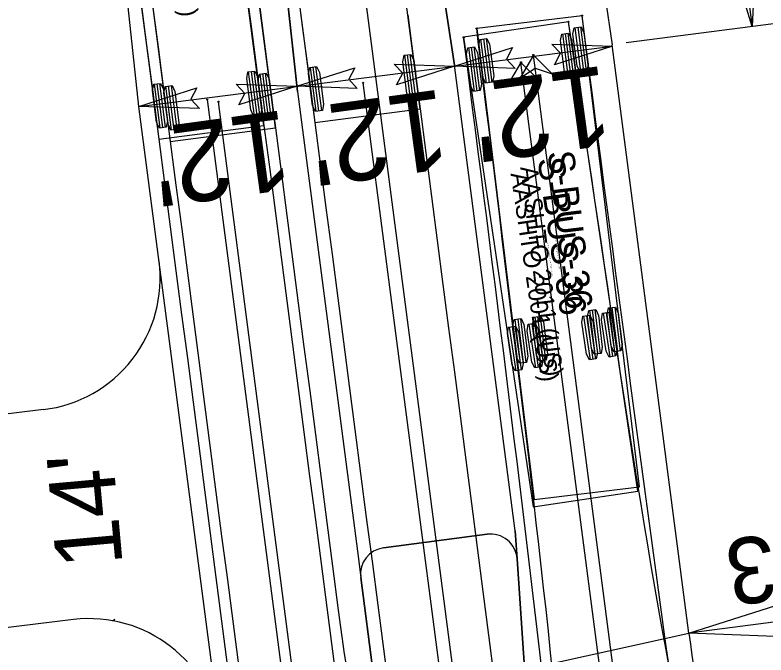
# Model space of a CAD drawing. Extents: x 2367848 to 2369479, y 800728 to 808616.
# Drawn here: x 2368338.9 to 2368395.5, y 808026 to 808074.3 of the extents above; entities that cross this region are included whole.
import ezdxf

# ---------------------------------------------------------------- set-up
doc = ezdxf.new("R2010")
doc.units = 0
for name, color, linetype in [('Prop AutoTurn Projected Path', 7, 'Continuous'), ('Prop AutoTurn Simulation', 7, 'Continuous'), ('Prop Conc 5in Monolithic Surface Mount Island', 7, 'Continuous'), ('Prop Dimension', 7, 'Continuous'), ('Prop Dimension Text', 7, 'Continuous'), ('Prop EOT', 7, 'Continuous'), ('Prop Horizontal Alignment', 7, 'Continuous'), ('Prop Lane Lines', 7, 'Continuous'), ('Prop Paint Stripe', 7, 'Continuous'), ('Prop Terminator CELL', 7, 'Continuous'), ('Scratch_Level_1', 7, 'Continuous'), ('Scratch_Level_3', 7, 'Continuous')]:
    doc.layers.add(name, color=color, linetype=linetype)

msp = doc.modelspace()

# ---------------------------------------------------------------- linework, layer by layer
at = {"layer": 'Prop AutoTurn Projected Path'}
for p, q in [((2368386.918, 807995.035), (2368377.058, 808070.767)), ((2368376.879, 807979.194), (2368365.158, 808069.218)), ((2368363.77, 807994.679), (2368354.25, 808067.798))]:
    msp.add_line(p, q, dxfattribs=at)
at = {"layer": 'Prop AutoTurn Simulation'}
for p, q in [((2368369.447, 808067.255), (2368364.825, 808102.755)), ((2368356.892, 808101.723), (2368361.514, 808066.222)), ((2368358.539, 808065.835), (2368353.917, 808101.335)), ((2368345.984, 808100.302), (2368350.606, 808064.802)), ((2368380.649, 808073.825), (2368372.735, 808072.655)), ((2368385.884, 808038.41), (2368380.649, 808073.825)), ((2368372.735, 808072.655), (2368377.97, 808037.24)), ((2368372.735, 808072.655), (2368372.735, 808072.655)), ((2368380.182, 808072.91), (2368380.612, 808069.604)), ((2368380.388, 808072.937), (2368380.819, 808069.631)), ((2368380.595, 808072.963), (2368381.025, 808069.658)), ((2368373.09, 808071.876), (2368373.521, 808068.571)), ((2368373.297, 808071.903), (2368373.727, 808068.597)), ((2368373.503, 808071.93), (2368373.934, 808068.624)), ((2368368.72, 808068.001), (2368368.29, 808071.306)), ((2368368.927, 808068.028), (2368368.496, 808071.333)), ((2368369.133, 808068.055), (2368368.703, 808071.36)), ((2368361.613, 808067.075), (2368361.183, 808070.381)), ((2368361.82, 808067.102), (2368361.39, 808070.408)), ((2368362.027, 808067.129), (2368361.596, 808070.435)), ((2368357.812, 808066.581), (2368357.382, 808069.886)), ((2368358.019, 808066.607), (2368357.588, 808069.913)), ((2368358.225, 808066.634), (2368357.795, 808069.94)), ((2368350.705, 808065.655), (2368350.275, 808068.961)), ((2368350.912, 808065.682), (2368350.482, 808068.988)), ((2368351.119, 808065.709), (2368350.688, 808069.015)), ((2368361.514, 808066.222), (2368369.447, 808067.255)), ((2368369.447, 808067.255), (2368369.447, 808067.255)), ((2368350.606, 808064.802), (2368358.539, 808065.835)), ((2368358.539, 808065.835), (2368358.539, 808065.835)), ((2368381.99, 808051.649), (2368382.477, 808048.352)), ((2368382.196, 808051.68), (2368382.683, 808048.382)), ((2368383.267, 808051.838), (2368383.755, 808048.541)), ((2368383.474, 808051.869), (2368383.961, 808048.571)), ((2368383.68, 808051.899), (2368384.167, 808048.602)), ((2368381.784, 808051.619), (2368382.271, 808048.321)), ((2368376.178, 808050.79), (2368376.665, 808047.493)), ((2368376.384, 808050.821), (2368376.871, 808047.523)), ((2368376.59, 808050.851), (2368377.077, 808047.554)), ((2368377.662, 808051.01), (2368378.149, 808047.712)), ((2368377.868, 808051.04), (2368378.355, 808047.743)), ((2368378.074, 808051.071), (2368378.561, 808047.773)), ((2368377.97, 808037.24), (2368385.884, 808038.41))]:
    msp.add_line(p, q, dxfattribs=at)
for points in [[(2368360.128, 808076.872), (2368360.59, 808073.322), (2368361.052, 808069.772), (2368361.514, 808066.222), (2368361.514, 808066.222), (2368361.514, 808066.222), (2368361.945, 808062.913), (2368362.376, 808059.603), (2368362.807, 808056.293), (2368363.238, 808052.983), (2368363.669, 808049.674), (2368364.1, 808046.364), (2368364.531, 808043.054), (2368364.962, 808039.745), (2368365.393, 808036.435), (2368365.824, 808033.125), (2368366.254, 808029.816), (2368366.685, 808026.506), (2368367.116, 808023.196)], [(2368357.153, 808076.485), (2368357.615, 808072.935), (2368358.077, 808069.385), (2368358.539, 808065.835), (2368358.539, 808065.835), (2368358.97, 808062.526), (2368359.401, 808059.218), (2368359.832, 808055.909), (2368360.263, 808052.601), (2368360.693, 808049.292), (2368361.124, 808045.984), (2368361.555, 808042.675), (2368361.986, 808039.367), (2368362.416, 808036.058), (2368362.847, 808032.75), (2368363.278, 808029.441), (2368363.732, 808026.136), (2368364.284, 808022.842)], [(2368349.22, 808075.452), (2368349.682, 808071.902), (2368350.144, 808068.352), (2368350.606, 808064.802), (2368350.606, 808064.802), (2368350.606, 808064.802), (2368351.037, 808061.494), (2368351.468, 808058.185), (2368351.899, 808054.876), (2368352.329, 808051.568), (2368352.76, 808048.259), (2368353.191, 808044.951), (2368353.622, 808041.642), (2368354.053, 808038.334), (2368354.483, 808035.025), (2368354.914, 808031.717), (2368355.345, 808028.408), (2368355.776, 808025.1)], [(2368368.523, 808074.355), (2368368.985, 808070.805), (2368369.447, 808067.255), (2368369.447, 808067.255), (2368369.878, 808063.945), (2368370.309, 808060.636), (2368370.74, 808057.326), (2368371.171, 808054.016), (2368371.602, 808050.707), (2368372.033, 808047.397), (2368372.464, 808044.087), (2368372.895, 808040.778), (2368373.326, 808037.468), (2368373.757, 808034.158), (2368374.187, 808030.849), (2368374.618, 808027.539), (2368375.049, 808024.229)], [(2368388.299, 808024.886), (2368388.007, 808026.448), (2368387.72, 808028.019), (2368387.438, 808029.597), (2368387.16, 808031.183), (2368386.886, 808032.774), (2368386.617, 808034.371), (2368386.351, 808035.973), (2368386.088, 808037.58), (2368385.829, 808039.19), (2368385.572, 808040.805), (2368385.319, 808042.422), (2368385.069, 808044.043), (2368384.82, 808045.667), (2368384.575, 808047.293), (2368384.331, 808048.921), (2368384.089, 808050.552), (2368383.848, 808052.184), (2368383.607, 808053.817), (2368383.365, 808055.452), (2368383.123, 808057.088), (2368382.881, 808058.725), (2368382.639, 808060.364), (2368382.397, 808062.003), (2368382.154, 808063.643), (2368381.912, 808065.283), (2368381.669, 808066.925), (2368381.426, 808068.567), (2368381.184, 808070.209), (2368380.941, 808071.853), (2368380.698, 808073.496), (2368380.649, 808073.825)], [(2368378.589, 808025.417), (2368378.389, 808027.123), (2368378.188, 808028.825), (2368377.986, 808030.523), (2368377.784, 808032.217), (2368377.581, 808033.908), (2368377.378, 808035.597), (2368377.174, 808037.283), (2368376.969, 808038.966), (2368376.764, 808040.647), (2368376.558, 808042.326), (2368376.352, 808044.003), (2368376.145, 808045.678), (2368375.937, 808047.351), (2368375.729, 808049.023), (2368375.521, 808050.694), (2368375.312, 808052.363), (2368375.102, 808054.031), (2368374.893, 808055.698), (2368374.682, 808057.364), (2368374.472, 808059.029), (2368374.261, 808060.694), (2368374.05, 808062.357), (2368373.839, 808064.02), (2368373.627, 808065.681), (2368373.415, 808067.343), (2368373.203, 808069.003), (2368372.99, 808070.664), (2368372.778, 808072.323), (2368372.735, 808072.655)]]:
    msp.add_lwpolyline(points, dxfattribs=at)
for points in [[(2368380.131, 808072.903), (2368380.646, 808072.97), (2368380.862, 808072.528), (2368381.172, 808070.148), (2368381.076, 808069.665), (2368380.561, 808069.598), (2368380.345, 808070.04), (2368380.035, 808072.42)], [(2368373.039, 808071.869), (2368373.554, 808071.936), (2368373.77, 808071.494), (2368374.08, 808069.114), (2368373.985, 808068.631), (2368373.469, 808068.564), (2368373.254, 808069.006), (2368372.944, 808071.386)], [(2368369.184, 808068.061), (2368368.669, 808067.994), (2368368.453, 808068.437), (2368368.143, 808070.817), (2368368.238, 808071.299), (2368368.754, 808071.367), (2368368.97, 808070.924), (2368369.28, 808068.544)], [(2368362.078, 808067.136), (2368361.562, 808067.069), (2368361.347, 808067.511), (2368361.037, 808069.891), (2368361.132, 808070.374), (2368361.647, 808070.441), (2368361.863, 808069.999), (2368362.173, 808067.619)], [(2368377.058, 808070.767), (2368376.055, 808069.036), (2368377.187, 808069.775), (2368378.47, 808069.351)], [(2368358.277, 808066.641), (2368357.761, 808066.574), (2368357.545, 808067.016), (2368357.235, 808069.396), (2368357.331, 808069.879), (2368357.846, 808069.946), (2368358.062, 808069.504), (2368358.372, 808067.124)], [(2368351.17, 808065.716), (2368350.654, 808065.649), (2368350.439, 808066.091), (2368350.129, 808068.471), (2368350.224, 808068.954), (2368350.739, 808069.021), (2368350.955, 808068.579), (2368351.265, 808066.199)], [(2368381.732, 808051.611), (2368382.247, 808051.687), (2368382.47, 808051.249), (2368382.821, 808048.874), (2368382.734, 808048.39), (2368382.22, 808048.314), (2368381.997, 808048.753), (2368381.646, 808051.127)], [(2368383.216, 808051.831), (2368383.731, 808051.907), (2368383.954, 808051.468), (2368384.305, 808049.094), (2368384.218, 808048.609), (2368383.704, 808048.533), (2368383.481, 808048.972), (2368383.13, 808051.346)], [(2368377.611, 808051.002), (2368378.125, 808051.078), (2368378.348, 808050.639), (2368378.699, 808048.265), (2368378.612, 808047.781), (2368378.098, 808047.705), (2368377.875, 808048.143), (2368377.524, 808050.517)], [(2368376.127, 808050.783), (2368376.641, 808050.859), (2368376.864, 808050.42), (2368377.215, 808048.046), (2368377.129, 808047.561), (2368376.614, 808047.485), (2368376.391, 808047.924), (2368376.04, 808050.298)]]:
    msp.add_lwpolyline(points, close=True, dxfattribs=at)
for centre in [(2368380.649, 808073.825), (2368372.735, 808072.655), (2368377.058, 808070.767), (2368365.158, 808069.218), (2368354.25, 808067.798)]:
    msp.add_circle(centre, 0.0417, dxfattribs=at)
at = {"layer": 'Prop Conc 5in Monolithic Surface Mount Island'}
for p, q in [((2368366.7, 808034.138), (2368374.509, 808035.154)), ((2368374.509, 808035.154), (2368366.7, 808034.138)), ((2368376.763, 808033.309), (2368378.903, 808002.305)), ((2368378.903, 808002.305), (2368376.763, 808033.309)), ((2368368.957, 808001.315), (2368364.975, 808031.896)), ((2368364.975, 808031.896), (2368368.957, 808001.315))]:
    msp.add_line(p, q, dxfattribs=at)
for centre, start, end in [((2368374.768, 808033.171), 3.9488, 97.418), ((2368374.768, 808033.171), 3.9488, 97.418), ((2368366.958, 808032.154), 97.418, 187.418), ((2368366.958, 808032.154), 97.418, 187.418)]:
    msp.add_arc(centre, 2, start, end, dxfattribs=at)
at = {"layer": 'Prop Dimension'}
for p, q in [((2368381.576, 808172.631), (2368394.487, 808073.468)), ((2368433.244, 808078.514), (2368384.987, 808072.231)), ((2368348.245, 808067.447), (2368383.958, 808071.988)), ((2368508.719, 808043.195), (2368389.724, 808027.702))]:
    msp.add_line(p, q, dxfattribs=at)
at = {"layer": 'Prop EOT'}
for p, q in [((2368339.442, 808368.833), (2368383.944, 808072.095)), ((2368348.245, 808067.447), (2368315.576, 808365.726)), ((2368389.724, 808027.702), (2368383.944, 808072.095)), ((2368354.432, 808019.926), (2368348.245, 808067.447)), ((2368341.037, 808044.564), (2368331.254, 808043.392)), ((2368343.306, 808028.721), (2368331.938, 808027.36)), ((2368346.238, 808028.636), (2368346.437, 808028.743))]:
    msp.add_line(p, q, dxfattribs=at)
for centre, radius, start, end in [((2368339.847, 808054.493), 10, 276.8294, 7.418), ((2368344.496, 808018.792), 10, 7.418, 96.8294), ((2368508.719, 808043.195), 120, 187.41804, 200.2566)]:
    msp.add_arc(centre, radius, start, end, dxfattribs=at)
at = {"layer": 'Prop Horizontal Alignment'}
msp.add_line((2368427.272, 807599.886), (2368315.244, 808460.338), dxfattribs=at)
at = {"layer": 'Prop Lane Lines'}
for p, q in [((2368360.202, 808068.573), (2368327.531, 808366.851)), ((2368327.595, 808366.859), (2368372.044, 808070.546)), ((2368360.202, 808068.573), (2368349.265, 808168.424))]:
    msp.add_line(p, q, dxfattribs=at)
at = {"layer": 'Prop Paint Stripe'}
for p, q in [((2368372.044, 808070.546), (2368327.595, 808366.859)), ((2368372.044, 808070.546), (2368327.595, 808366.859)), ((2368349.265, 808168.424), (2368360.202, 808068.573)), ((2368372.034, 808070.544), (2368372.044, 808070.546)), ((2368372.034, 808070.544), (2368372.044, 808070.546)), ((2368376.616, 808035.429), (2368372.034, 808070.544)), ((2368376.616, 808035.429), (2368372.034, 808070.544)), ((2368360.202, 808068.573), (2368364.717, 808033.879)), ((2368360.202, 808068.573), (2368364.717, 808033.879)), ((2368376.616, 808035.429), (2368376.763, 808033.309)), ((2368376.763, 808033.309), (2368376.616, 808035.429)), ((2368366.7, 808034.138), (2368374.509, 808035.154)), ((2368364.717, 808033.879), (2368364.975, 808031.896)), ((2368364.717, 808033.879), (2368364.975, 808031.896))]:
    msp.add_line(p, q, dxfattribs=at)
msp.add_lwpolyline([(2368327.531, 808366.851), (2368349.265, 808168.424), (2368360.202, 808068.573)], dxfattribs=at)
for centre, start, end in [((2368374.768, 808033.171), 3.9488, 97.418), ((2368366.958, 808032.154), 97.418, 187.418)]:
    msp.add_arc(centre, 2, start, end, dxfattribs=at)
at = {"layer": 'Prop Terminator CELL'}
for points in [[(2368394.936, 808082.589), (2368394.487, 808073.468), (2368391.803, 808082.258), (2368393.53, 808081.31)], [(2368379.394, 808072.148), (2368383.958, 808071.988), (2368379.582, 808070.584), (2368380.044, 808071.454)], [(2368376.617, 808070.314), (2368372.053, 808070.474), (2368376.429, 808071.878), (2368375.967, 808071.008)], [(2368364.713, 808068.801), (2368360.149, 808068.961), (2368364.525, 808070.365), (2368364.063, 808069.494)], [(2368367.49, 808070.634), (2368372.053, 808070.474), (2368367.678, 808069.07), (2368368.14, 808069.941)], [(2368352.809, 808067.287), (2368348.245, 808067.447), (2368352.621, 808068.851), (2368352.159, 808067.981)], [(2368355.586, 808069.121), (2368360.149, 808068.961), (2368355.774, 808067.557), (2368356.236, 808068.427)], [(2368398.849, 808027.35), (2368389.724, 808027.702), (2368398.485, 808030.479), (2368397.555, 808028.741)]]:
    msp.add_lwpolyline(points, close=True, dxfattribs=at)
at = {"layer": 'Scratch_Level_1'}
for p, q in [((2368357.676, 808065.996), (2368353.054, 808101.496)), ((2368345.121, 808100.463), (2368349.743, 808064.963)), ((2368381.663, 808074.286), (2368373.721, 808073.319)), ((2368385.989, 808038.748), (2368381.663, 808074.286)), ((2368373.721, 808073.319), (2368378.048, 808037.781)), ((2368373.721, 808073.319), (2368373.721, 808073.319)), ((2368381.129, 808073.383), (2368381.559, 808070.077)), ((2368381.336, 808073.41), (2368381.766, 808070.104)), ((2368381.542, 808073.437), (2368381.972, 808070.131)), ((2368374.016, 808072.51), (2368374.446, 808069.204)), ((2368374.222, 808072.537), (2368374.653, 808069.231)), ((2368374.429, 808072.564), (2368374.859, 808069.258)), ((2368389.849, 807980.271), (2368377.994, 808071.32)), ((2368356.948, 808066.741), (2368356.518, 808070.047)), ((2368357.155, 808066.768), (2368356.725, 808070.074)), ((2368357.362, 808066.795), (2368356.931, 808070.1)), ((2368349.842, 808065.816), (2368349.411, 808069.121)), ((2368350.048, 808065.843), (2368349.618, 808069.148)), ((2368350.255, 808065.87), (2368349.825, 808069.175)), ((2368353.386, 808067.958), (2368365.308, 807976.394)), ((2368349.743, 808064.963), (2368357.676, 808065.996)), ((2368357.676, 808065.996), (2368357.676, 808065.996)), ((2368383.717, 808052.239), (2368384.12, 808048.93)), ((2368383.924, 808052.264), (2368384.327, 808048.955)), ((2368384.131, 808052.289), (2368384.533, 808048.98)), ((2368382.228, 808052.058), (2368382.631, 808048.749)), ((2368382.435, 808052.083), (2368382.838, 808048.774)), ((2368382.642, 808052.108), (2368383.044, 808048.799)), ((2368376.603, 808051.373), (2368377.006, 808048.064)), ((2368376.81, 808051.398), (2368377.213, 808048.089)), ((2368377.017, 808051.423), (2368377.419, 808048.114)), ((2368378.092, 808051.554), (2368378.495, 808048.245)), ((2368378.299, 808051.579), (2368378.702, 808048.27)), ((2368378.506, 808051.604), (2368378.908, 808048.296)), ((2368378.048, 808037.781), (2368385.989, 808038.748))]:
    msp.add_line(p, q, dxfattribs=at)
for points in [[(2368356.289, 808076.646), (2368356.751, 808073.096), (2368357.214, 808069.546), (2368357.676, 808065.996), (2368357.676, 808065.996), (2368358.106, 808062.69), (2368358.537, 808059.384), (2368358.967, 808056.079), (2368359.397, 808052.773), (2368359.828, 808049.468), (2368360.258, 808046.162), (2368360.688, 808042.856), (2368361.119, 808039.551), (2368361.549, 808036.245), (2368361.98, 808032.94), (2368362.41, 808029.634), (2368362.84, 808026.329), (2368363.271, 808023.023)], [(2368348.356, 808075.613), (2368348.818, 808072.063), (2368349.281, 808068.513), (2368349.743, 808064.963), (2368349.743, 808064.963), (2368349.743, 808064.963), (2368350.173, 808061.657), (2368350.603, 808058.352), (2368351.034, 808055.046), (2368351.464, 808051.74), (2368351.895, 808048.435), (2368352.325, 808045.129), (2368352.755, 808041.824), (2368353.186, 808038.518), (2368353.616, 808035.212), (2368354.047, 808031.907), (2368354.477, 808028.601), (2368354.907, 808025.296)], [(2368388.254, 808025.002), (2368388.022, 808026.681), (2368387.79, 808028.359), (2368387.56, 808030.035), (2368387.331, 808031.709), (2368387.103, 808033.382), (2368386.876, 808035.053), (2368386.649, 808036.724), (2368386.423, 808038.393), (2368386.198, 808040.061), (2368385.974, 808041.728), (2368385.75, 808043.394), (2368385.527, 808045.059), (2368385.305, 808046.724), (2368385.083, 808048.388), (2368384.861, 808050.051), (2368384.64, 808051.714), (2368384.419, 808053.376), (2368384.199, 808055.037), (2368383.979, 808056.699), (2368383.759, 808058.359), (2368383.54, 808060.02), (2368383.32, 808061.679), (2368383.102, 808063.339), (2368382.883, 808064.998), (2368382.665, 808066.657), (2368382.447, 808068.316), (2368382.229, 808069.975), (2368382.011, 808071.633), (2368381.793, 808073.291), (2368381.663, 808074.286)], [(2368379.465, 808024.577), (2368379.296, 808026.208), (2368379.123, 808027.841), (2368378.947, 808029.476), (2368378.768, 808031.112), (2368378.586, 808032.751), (2368378.402, 808034.39), (2368378.216, 808036.031), (2368378.027, 808037.674), (2368377.836, 808039.317), (2368377.644, 808040.962), (2368377.45, 808042.607), (2368377.254, 808044.254), (2368377.056, 808045.901), (2368376.858, 808047.548), (2368376.658, 808049.197), (2368376.457, 808050.846), (2368376.256, 808052.495), (2368376.055, 808054.146), (2368375.854, 808055.796), (2368375.653, 808057.448), (2368375.452, 808059.099), (2368375.251, 808060.752), (2368375.05, 808062.404), (2368374.849, 808064.057), (2368374.648, 808065.71), (2368374.446, 808067.364), (2368374.245, 808069.018), (2368374.044, 808070.672), (2368373.842, 808072.326), (2368373.721, 808073.319)]]:
    msp.add_lwpolyline(points, dxfattribs=at)
for points in [[(2368381.078, 808073.376), (2368381.593, 808073.443), (2368381.809, 808073.001), (2368382.119, 808070.621), (2368382.024, 808070.138), (2368381.508, 808070.071), (2368381.292, 808070.513), (2368380.983, 808072.893)], [(2368373.964, 808072.503), (2368374.48, 808072.57), (2368374.696, 808072.128), (2368375.006, 808069.748), (2368374.91, 808069.265), (2368374.395, 808069.198), (2368374.179, 808069.64), (2368373.869, 808072.02)], [(2368377.994, 808071.32), (2368376.992, 808069.59), (2368378.123, 808070.329), (2368379.406, 808069.904)], [(2368357.413, 808066.802), (2368356.897, 808066.735), (2368356.682, 808067.177), (2368356.372, 808069.557), (2368356.467, 808070.04), (2368356.982, 808070.107), (2368357.198, 808069.665), (2368357.508, 808067.285)], [(2368350.306, 808065.876), (2368349.79, 808065.809), (2368349.575, 808066.252), (2368349.265, 808068.632), (2368349.36, 808069.115), (2368349.876, 808069.182), (2368350.091, 808068.739), (2368350.401, 808066.359)], [(2368383.666, 808052.233), (2368384.182, 808052.296), (2368384.394, 808051.851), (2368384.684, 808049.469), (2368384.585, 808048.987), (2368384.069, 808048.924), (2368383.857, 808049.368), (2368383.567, 808051.75)], [(2368382.177, 808052.051), (2368382.693, 808052.114), (2368382.905, 808051.67), (2368383.195, 808049.288), (2368383.096, 808048.805), (2368382.58, 808048.743), (2368382.368, 808049.187), (2368382.078, 808051.569)], [(2368376.552, 808051.367), (2368377.068, 808051.429), (2368377.28, 808050.985), (2368377.57, 808048.603), (2368377.471, 808048.121), (2368376.954, 808048.058), (2368376.743, 808048.502), (2368376.452, 808050.884)], [(2368378.041, 808051.548), (2368378.557, 808051.611), (2368378.769, 808051.166), (2368379.059, 808048.784), (2368378.96, 808048.302), (2368378.443, 808048.239), (2368378.232, 808048.683), (2368377.941, 808051.066)]]:
    msp.add_lwpolyline(points, close=True, dxfattribs=at)
for centre in [(2368381.663, 808074.286), (2368373.721, 808073.319), (2368377.994, 808071.32), (2368353.386, 808067.958)]:
    msp.add_circle(centre, 0.0417, dxfattribs=at)
at = {"layer": 'Scratch_Level_3'}
msp.add_line((2368354.432, 808019.926), (2368389.724, 808027.702), dxfattribs=at)

# ---------------------------------------------------------------- texts
at = {"layer": 'Prop AutoTurn Simulation'}
for s, height, rotation, p in [('AASHTO 2001 (US)', 1.33333, 277.418, (2368349.341, 808089.963)), ('S-BUS-36', 2, 278.4087, (2368378.298, 808063.47)), ('AASHTO 2001 (US)', 1.33333, 278.4087, (2368376.27, 808062.376)), ('(c) 2014 Transoft Solutions, Inc. All rights reserved.', 0.08, 278.4087, (2368379.032, 808057.14))]:
    msp.add_text(s, height=height, rotation=rotation, dxfattribs=at).set_placement(p)
at = {"layer": 'Prop Dimension'}
for s, height, rotation, p in [("12'", 6, 187.7641, (2368383.399, 808070.538)), ("12'", 6, 187.7641, (2368371.117, 808068.752)), ("12'", 6, 187.7641, (2368359.253, 808067.19)), ("14'", 5, 95.1308, (2368347.024, 808032.849))]:
    msp.add_text(s, height=height, rotation=rotation, dxfattribs=at).set_placement(p)
at = {"layer": 'Prop Dimension Text'}
msp.add_text('+25.23', height=5, rotation=187.1063, dxfattribs=at).set_placement((2368412.758, 808037.257))
at = {"layer": 'Scratch_Level_1'}
for s, height, p in [('S-BUS-36', 2, (2368379.047, 808063.994)), ('AASHTO 2011 (US)', 1.33333, (2368377.003, 808062.858)), ('(c) 2016 Transoft Solutions, Inc. All rights reserved.', 0.08, (2368379.618, 808057.647))]:
    msp.add_text(s, height=height, rotation=276.9412, dxfattribs=at).set_placement(p)

doc.saveas('drawing.dxf')
